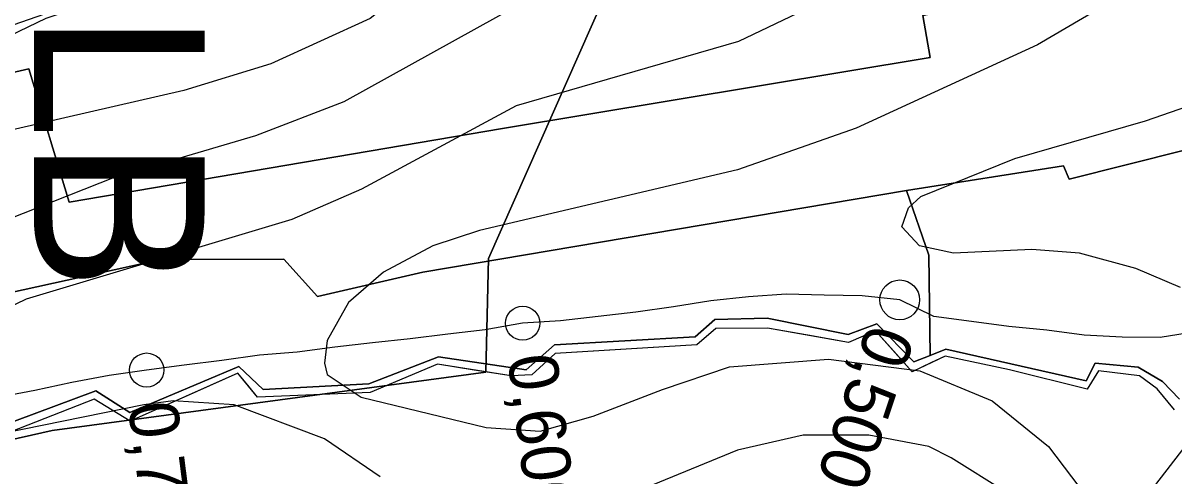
# Model space of a CAD drawing. Extents: x -510989 to -501240, y -1184665 to -1176098.
# Drawn here: x -510017.7 to -509714, y -1180896.8 to -1180777.2 of the extents above; entities that cross this region are included whole.
import ezdxf

# ---------------------------------------------------------------- set-up
doc = ezdxf.new("R2010")
doc.units = 0
for name, color, linetype in [('ostatni_plocha_x_neplodna_puda', 7, 'Continuous'), ('popis', 7, 'Continuous'), ('STAV_USES', 7, 'Continuous'), ('trasovani_toku', 7, 'Continuous'), ('trvaly_travni_porost', 7, 'Continuous'), ('vodni_plocha_x_vodni_tok_v_koryt_prir_n_upr', 7, 'Continuous'), ('vodni_plocha_x_zamokrena_plocha', 7, 'Continuous'), ('vrstevnice_01', 7, 'Continuous'), ('vrstevnice_02', 7, 'Continuous')]:
    doc.layers.add(name, color=color, linetype=linetype)

msp = doc.modelspace()

# ---------------------------------------------------------------- linework, layer by layer
at = {"layer": 'ostatni_plocha_x_neplodna_puda'}
msp.add_lwpolyline([(-509765.69, -1180726.57), (-509779.19, -1180769.29), (-509780.55, -1180773.57), (-509780.27, -1180775.21), (-509778.41, -1180786.28), (-509891.24, -1180805.07), (-510005.55, -1180824.51), (-510016.18, -1180789.31), (-510028.05, -1180792.05), (-510041.12, -1180794.43), (-510042.68, -1180785.9), (-510069.65, -1180791.93), (-510094.49, -1180794.45), (-510093.08, -1180792.66), (-510079.25, -1180791.33), (-510022.29, -1180778.39), (-509997.82, -1180769.77), (-509931.53, -1180746.42), (-509899.09, -1180738.43), (-509794.45, -1180721.7)], close=True, dxfattribs=at)
at = {"layer": 'popis'}
msp.add_lwpolyline([(-509713.91, -1180879.3), (-509718.51, -1180873.81), (-509723.12, -1180870.38), (-509733.99, -1180869.01), (-509736.98, -1180873.9), (-509757.46, -1180868.8), (-509774.42, -1180865.17), (-509783.09, -1180869.29), (-509787.94, -1180863.89), (-509792.79, -1180858.49), (-509799.95, -1180861.53), (-509810.61, -1180859.64), (-509821.28, -1180857.74), (-509834.91, -1180857.83), (-509839.9, -1180862.15), (-509858.59, -1180863.32), (-509877.28, -1180864.5), (-509883.47, -1180870.09), (-509888.95, -1180870.39), (-509898.64, -1180868.82), (-509908.32, -1180867.25), (-509926.11, -1180874.78), (-509940.96, -1180875.36), (-509955.81, -1180875.95), (-509958.41, -1180872.81), (-509961, -1180869.68), (-509975.23, -1180876.01), (-509989.47, -1180882.33), (-509998.97, -1180876.54), (-510020.89, -1180885.17)], dxfattribs=at)
at = {"layer": 'STAV_USES'}
for p, q in [((-509844.54, -1180725.68), (-509894.94, -1180839.35)), ((-509894.94, -1180839.35), (-509844.54, -1180725.68)), ((-509894.94, -1180839.35), (-509895.58, -1180869.35)), ((-509895.58, -1180869.35), (-509894.94, -1180839.35)), ((-509895.58, -1180869.35), (-510009.99, -1180884.81)), ((-510009.99, -1180884.81), (-509895.58, -1180869.35)), ((-510009.99, -1180884.81), (-510054.67, -1180894.92)), ((-510054.67, -1180894.92), (-510009.99, -1180884.81))]:
    msp.add_line(p, q, dxfattribs=at)
at = {"layer": 'trasovani_toku'}
for p, q in [((-509826.32, -1180849.53), (-509836.27, -1180850.52)), ((-509816.34, -1180848.83), (-509826.32, -1180849.53)), ((-509806.35, -1180849.05), (-509816.34, -1180848.83)), ((-509796.35, -1180849.27), (-509806.35, -1180849.05)), ((-509786.4, -1180850.3), (-509796.35, -1180849.27)), ((-509846.13, -1180852.17), (-509856.03, -1180853.59)), ((-509836.27, -1180850.52), (-509846.13, -1180852.17)), ((-509777.41, -1180854.67), (-509786.4, -1180850.3)), ((-509875.91, -1180855.8), (-509885.89, -1180856.47)), ((-509865.97, -1180854.7), (-509875.91, -1180855.8)), ((-509856.03, -1180853.59), (-509865.97, -1180854.7)), ((-509767.49, -1180855.97), (-509777.41, -1180854.67)), ((-509757.59, -1180857.36), (-509767.49, -1180855.97)), ((-509895.74, -1180858.19), (-509905.67, -1180859.38)), ((-509885.89, -1180856.47), (-509895.74, -1180858.19)), ((-509747.63, -1180858.32), (-509757.59, -1180857.36)), ((-509737.72, -1180859.59), (-509747.63, -1180858.32)), ((-509707.86, -1180858.69), (-509717.73, -1180860.28)), ((-509925.54, -1180861.65), (-509935.47, -1180862.8)), ((-509915.6, -1180860.56), (-509925.54, -1180861.65)), ((-509905.67, -1180859.38), (-509915.6, -1180860.56)), ((-509727.73, -1180860.11), (-509737.72, -1180859.59)), ((-509717.73, -1180860.28), (-509727.73, -1180860.11)), ((-509955.36, -1180864.88), (-509965.26, -1180866.27)), ((-509945.39, -1180864.08), (-509955.36, -1180864.88)), ((-509935.47, -1180862.8), (-509945.39, -1180864.08)), ((-509975.18, -1180867.52), (-509985.09, -1180868.83)), ((-509965.26, -1180866.27), (-509975.18, -1180867.52)), ((-509994.99, -1180870.3), (-510004.81, -1180872.15)), ((-509985.09, -1180868.83), (-509994.99, -1180870.3)), ((-510014.59, -1180874.27), (-510024.42, -1180876.08)), ((-510004.81, -1180872.15), (-510014.59, -1180874.27))]:
    msp.add_line(p, q, dxfattribs=at)
for centre, radius in [((-509786.4, -1180850.3), 5.25), ((-509885.89, -1180856.47), 4.5), ((-509985.09, -1180868.83), 4.5)]:
    msp.add_circle(centre, radius, dxfattribs=at)
at = {"layer": 'trvaly_travni_porost'}
for points in [[(-510028.05, -1180792.05), (-510016.18, -1180789.31), (-510005.55, -1180824.51), (-509891.24, -1180805.07), (-509778.41, -1180786.28), (-509780.27, -1180775.21), (-509719.45, -1180761.75), (-509753.6, -1180764.23), (-509779.19, -1180769.29), (-509765.69, -1180726.57), (-509763.26, -1180726.98), (-509700.64, -1180738.29)], [(-509711.28, -1180810.81), (-509741.72, -1180818.44), (-509743.19, -1180814.91), (-509784.6, -1180821.47), (-509912.19, -1180842.95), (-509939.98, -1180849.43), (-509948.94, -1180839.54), (-509981.23, -1180839.63), (-510022.06, -1180848.63)], [(-509712.58, -1180876.52), (-509717.05, -1180871.87), (-509723.45, -1180868.07), (-509734.84, -1180866.99), (-509737.17, -1180871.71), (-509774.25, -1180863.3), (-509778.38, -1180864.95), (-509778.72, -1180838.53), (-509784.6, -1180821.47), (-509743.19, -1180814.91), (-509741.72, -1180818.44), (-509711.28, -1180810.81)]]:
    msp.add_lwpolyline(points, dxfattribs=at)
at = {"layer": 'vodni_plocha_x_vodni_tok_v_koryt_prir_n_upr'}
for points in [[(-510019.95, -1180882.36), (-509998.46, -1180874.36), (-509989.5, -1180880), (-509960.8, -1180867.93), (-509954.38, -1180873.98), (-509926.45, -1180872.49), (-509908.11, -1180865.38), (-509884.93, -1180868.81), (-509877.51, -1180862.21), (-509840.4, -1180860.07), (-509835.22, -1180855.46), (-509821.4, -1180855.13), (-509800.01, -1180859.44), (-509792.44, -1180856.66), (-509782.67, -1180866.66), (-509778.38, -1180864.95), (-509774.25, -1180863.3), (-509737.17, -1180871.71), (-509734.84, -1180866.99), (-509723.45, -1180868.07), (-509717.05, -1180871.87), (-509712.58, -1180876.52)], [(-509713.91, -1180879.3), (-509718.51, -1180873.81), (-509723.12, -1180870.38), (-509733.99, -1180869.01), (-509736.98, -1180873.9), (-509757.46, -1180868.8), (-509774.42, -1180865.17), (-509778.16, -1180866.95), (-509783.09, -1180869.29), (-509792.79, -1180858.49), (-509799.95, -1180861.53), (-509821.28, -1180857.74), (-509834.91, -1180857.83), (-509839.9, -1180862.15), (-509877.28, -1180864.5), (-509883.47, -1180870.09), (-509888.95, -1180870.39), (-509908.32, -1180867.25), (-509926.11, -1180874.78), (-509955.81, -1180875.95), (-509961, -1180869.68), (-509989.47, -1180882.33), (-509998.97, -1180876.54), (-510020.89, -1180885.17)]]:
    msp.add_lwpolyline(points, dxfattribs=at)
at = {"layer": 'vodni_plocha_x_zamokrena_plocha'}
msp.add_lwpolyline([(-510022.06, -1180848.63), (-509981.23, -1180839.63), (-509948.94, -1180839.54), (-509939.98, -1180849.43), (-509912.19, -1180842.95), (-509784.6, -1180821.47), (-509778.72, -1180838.53), (-509778.38, -1180864.95), (-509782.67, -1180866.66), (-509792.44, -1180856.66), (-509800.01, -1180859.44), (-509821.4, -1180855.13), (-509835.22, -1180855.46), (-509840.4, -1180860.07), (-509877.51, -1180862.21), (-509884.93, -1180868.81), (-509908.11, -1180865.38), (-509926.45, -1180872.49), (-509954.38, -1180873.98), (-509960.8, -1180867.93), (-509989.5, -1180880), (-509998.46, -1180874.36), (-510019.95, -1180882.36)], dxfattribs=at)
at = {"layer": 'vrstevnice_01'}
for points in [[(-509655.91, -1180542), (-509647.59, -1180565), (-509647.81, -1180586), (-509658.19, -1180623), (-509663.19, -1180653), (-509672.19, -1180677), (-509679.41, -1180686), (-509687, -1180693), (-509693.41, -1180696), (-509735.31, -1180709), (-509747.81, -1180715), (-509753.5, -1180723), (-509778, -1180732), (-509811.09, -1180746), (-509864.09, -1180761), (-509880.81, -1180769), (-509933.09, -1180798), (-509956.41, -1180807), (-509993.69, -1180818), (-510021.41, -1180829)], [(-509711.09, -1180546), (-509710.91, -1180563), (-509721.41, -1180585), (-509730.41, -1180615), (-509739.91, -1180625), (-509751, -1180631), (-509757.59, -1180637), (-509770.81, -1180653), (-509778.69, -1180650), (-509782.5, -1180650), (-509840.31, -1180699), (-509848.5, -1180701), (-509851, -1180702), (-509853.31, -1180711), (-509880.5, -1180713), (-509905.81, -1180721), (-509928.91, -1180731), (-509946.31, -1180743), (-509966.91, -1180761), (-510011.69, -1180776), (-510028.41, -1180784)], [(-509706.09, -1180759), (-509726.31, -1180769), (-509750.09, -1180783), (-509797.91, -1180805), (-509829.19, -1180816), (-509897.31, -1180832), (-509909.59, -1180836), (-509922.59, -1180843), (-509931.81, -1180851), (-509937.5, -1180861), (-509938.19, -1180867), (-509937.5, -1180870), (-509928.5, -1180876), (-509895.5, -1180884), (-509881.31, -1180885), (-509867.31, -1180881), (-509849, -1180874), (-509831.31, -1180868), (-509805.19, -1180866), (-509781.09, -1180869), (-509762, -1180877), (-509747.19, -1180889), (-509735, -1180905)], [(-509724.19, -1180906), (-509711.09, -1180889), (-509704.69, -1180885), (-509689.19, -1180881), (-509657.81, -1180888), (-509641, -1180888), (-509572.31, -1180876), (-509538.41, -1180873), (-509515.41, -1180874), (-509494.09, -1180878), (-509470.41, -1180887), (-509458.81, -1180894), (-509444.5, -1180905)]]:
    msp.add_lwpolyline(points, dxfattribs=at)
at = {"layer": 'vrstevnice_02'}
for points in [[(-510056.09, -1180869), (-510016.81, -1180850), (-509946.69, -1180829), (-509928.31, -1180821), (-509887.5, -1180799), (-509828.81, -1180782), (-509772.5, -1180755), (-509745.81, -1180746), (-509712.31, -1180736), (-509706.5, -1180733), (-509702.5, -1180723), (-509686.69, -1180720), (-509671, -1180714), (-509658.31, -1180705), (-509644.69, -1180688), (-509623.19, -1180638), (-509613.41, -1180605), (-509612.19, -1180590), (-509612.91, -1180582), (-509616.91, -1180569), (-509633.19, -1180540)], [(-509680, -1180557), (-509680.91, -1180568), (-509690.59, -1180610), (-509690, -1180642), (-509692.41, -1180653), (-509696.41, -1180662), (-509700.09, -1180666), (-509716.31, -1180681), (-509730.09, -1180687), (-509750.59, -1180695), (-509769.91, -1180706), (-509789.41, -1180708), (-509792.5, -1180717), (-509835.91, -1180732), (-509872.19, -1180741), (-509894.81, -1180751), (-509926.09, -1180776), (-509952.31, -1180788), (-509975.31, -1180795), (-510031.69, -1180808)], [(-509712.31, -1180847), (-509724.09, -1180842), (-509739, -1180838), (-509751.59, -1180837), (-509772.19, -1180838), (-509781.19, -1180836), (-509785.81, -1180831), (-509784.09, -1180826), (-509780.81, -1180823), (-509756, -1180813), (-509721.59, -1180803), (-509684, -1180790)], [(-509923.5, -1180897), (-509938.19, -1180887), (-509962, -1180878), (-509978.09, -1180877), (-509985.81, -1180878), (-510049.91, -1180891)], [(-509758.5, -1180901), (-509772.81, -1180892), (-509778.69, -1180889), (-509794.59, -1180886), (-509811.91, -1180886), (-509829.19, -1180890), (-509858.59, -1180902)]]:
    msp.add_lwpolyline(points, dxfattribs=at)

# ---------------------------------------------------------------- texts
at = {"layer": 'STAV_USES'}
msp.add_text('LB', height=45, rotation=270, dxfattribs=at).set_placement((-510014.82, -1180774.27))
at = {"layer": 'trasovani_toku'}
for s, rotation, p in [('0,500', 251.5723, (-509794.63, -1180856.1)), ('0,600', 277.3493, (-509889.91, -1180865.46)), ('0,700', 277.3027, (-509990.05, -1180878.01))]:
    msp.add_text(s, height=13, rotation=rotation, dxfattribs=at).set_placement(p)

doc.saveas('drawing.dxf')
